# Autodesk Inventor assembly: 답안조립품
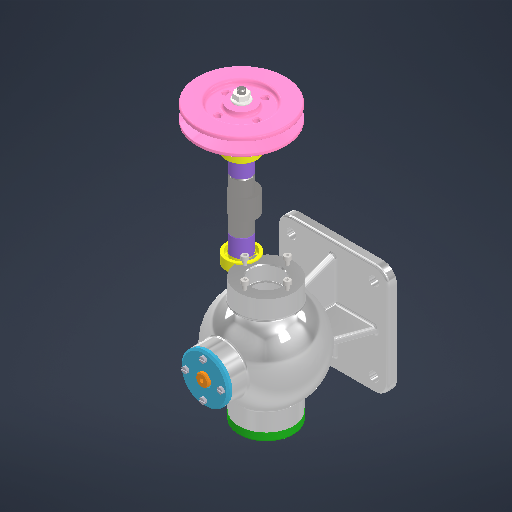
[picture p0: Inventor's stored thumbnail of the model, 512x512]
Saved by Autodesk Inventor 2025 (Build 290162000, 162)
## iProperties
Created: 2025-08
Part Number: 답안조립품
Document SubType Name: Assembly
Designer: infra15
Author: infra15
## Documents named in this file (15)
- C:\Users\infra15\Desktop\750807V1010\답안조립품.iam
- C:\Users\infra15\Desktop\750807V1010\본체.ipt
- C:\Users\infra15\Desktop\750807V1010\V-벨트풀리\V-벨트풀리.ipt
- C:\Users\infra15\Desktop\750807V1010\너트 M8\너트 M8.ipt
- C:\Users\infra15\Desktop\750807V1010\뒤커버\뒤커버.ipt
- C:\Users\infra15\Desktop\750807V1010\베어링- 6202\베어링- 6202.ipt
- C:\Users\infra15\Desktop\750807V1010\볼트 M4 x 12\볼트 M4 x 12.ipt
- C:\Users\infra15\Desktop\750807V1010\볼트 M4 x 16\볼트 M4 x 16.ipt
- C:\Users\infra15\Desktop\750807V1010\상부커버\상부커버.ipt
- C:\Users\infra15\Desktop\750807V1010\슬라이드\슬라이드.ipt
- C:\Users\infra15\Desktop\750807V1010\앞커버\앞커버.ipt
- C:\Users\infra15\Desktop\750807V1010\칼라\칼라.ipt
- C:\Users\infra15\Desktop\750807V1010\키 4 x 4 x 12\키 4 x 4 x 12.ipt
- C:\Users\infra15\Desktop\750807V1010\편심축\편심축.ipt
- C:\Users\infra15\Desktop\750807V1010\오일실 15 30 7\오일실 15 30 7.ipt
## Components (1 placed, 1 different names)
1. V-벨트풀리:1
